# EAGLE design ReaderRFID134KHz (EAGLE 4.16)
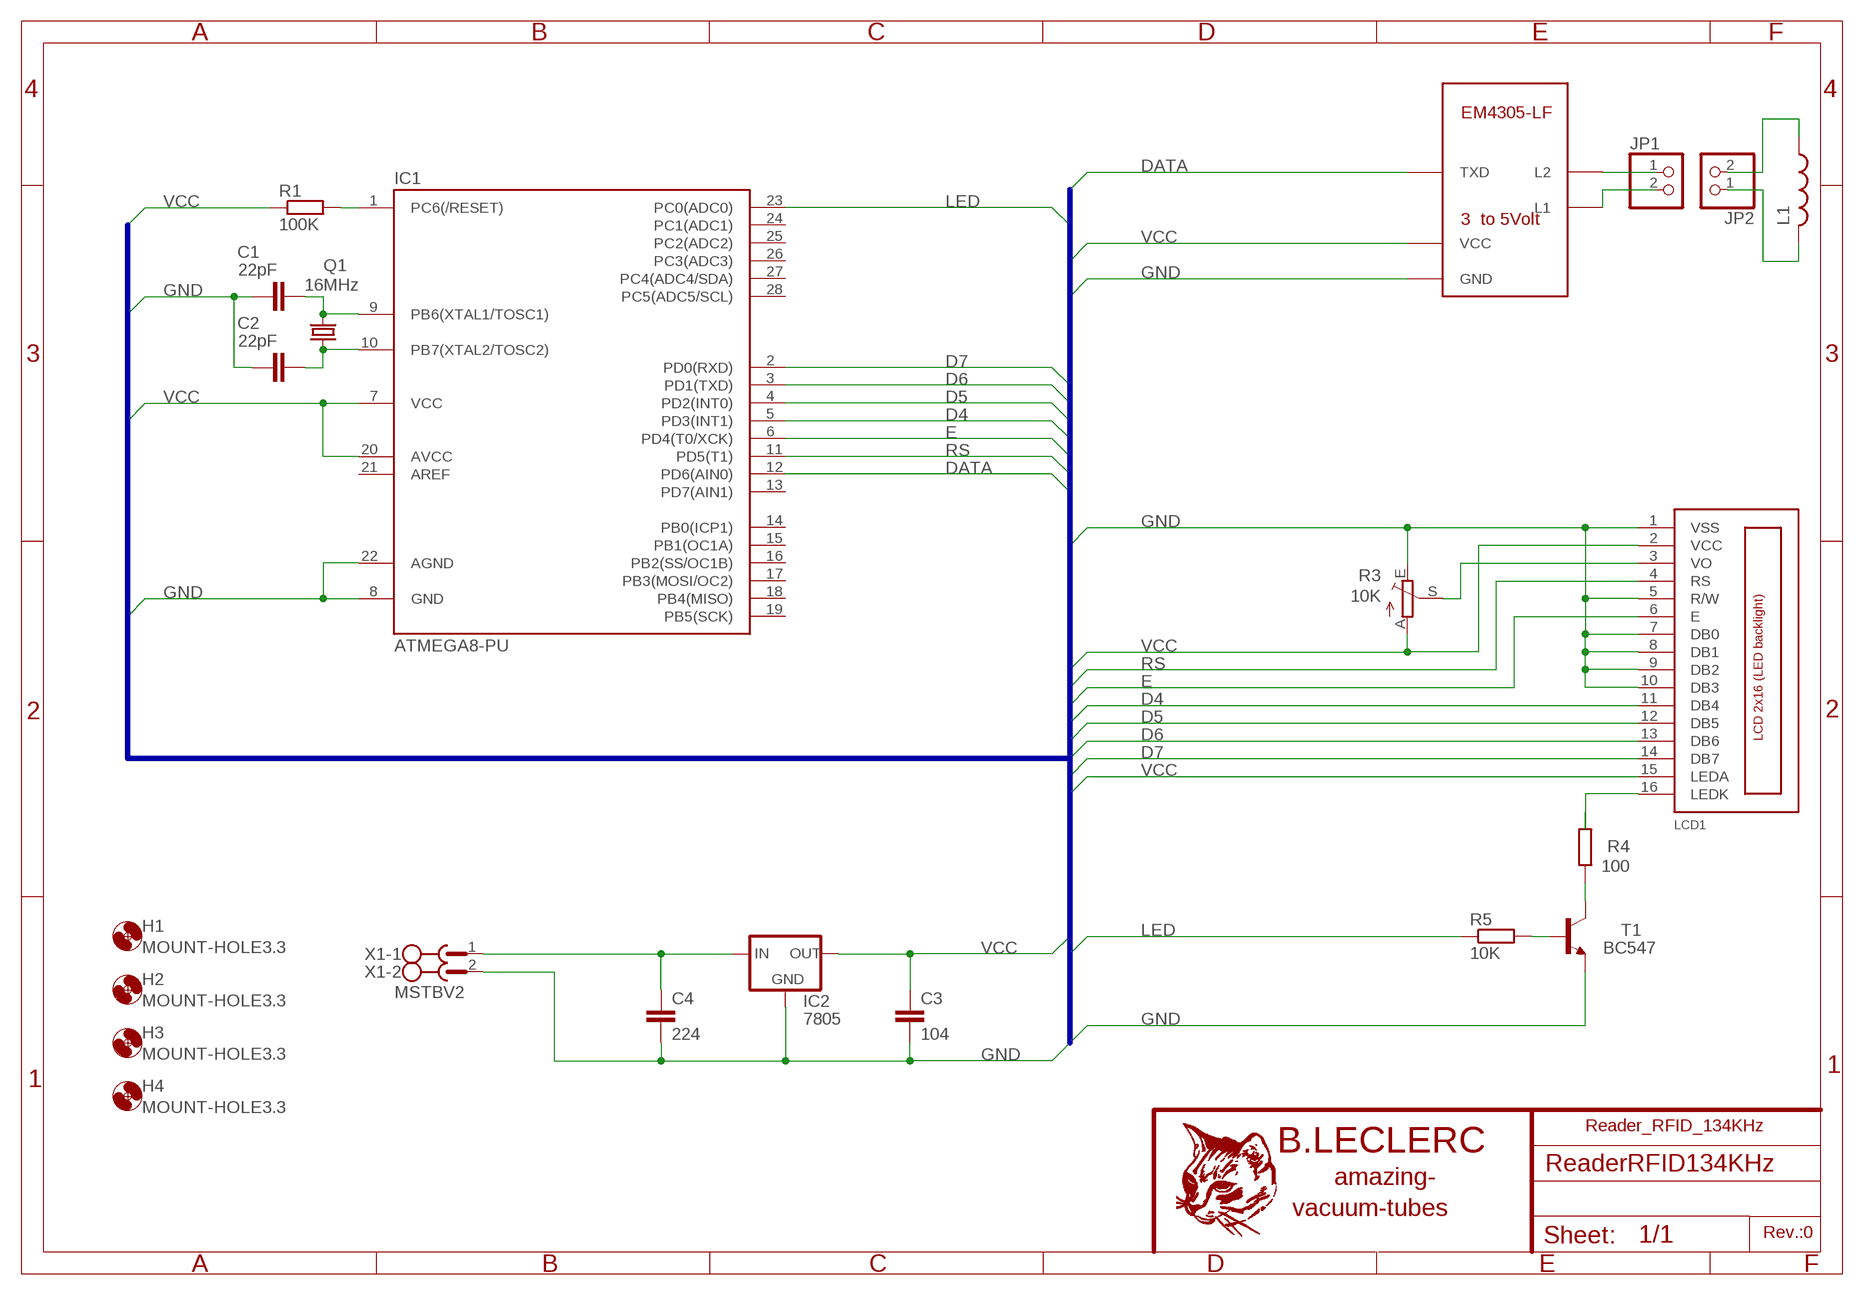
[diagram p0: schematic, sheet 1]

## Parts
C1  22pF  C-EU025-030X050  [C025-030X050]
C2  22pF  C-EU025-030X050  [C025-030X050]
C3  104  C-EU050-025X075  [C050-025X075]
C4  224  C-EU050-035X075  [C050-035X075]
H1  MOUNT-HOLE3.3  [3,3]
H2  MOUNT-HOLE3.3  [3,3]
H3  MOUNT-HOLE3.3  [3,3]
H4  MOUNT-HOLE3.3  [3,3]
IC1  ATMEGA8-PU  [DIL28-3]
IC2  7805  78XXL  [78XXL]
JP1  PINHD-1X2  [1X02]
JP2  PINHD-1X2  [1X02]
L1  L-US0207/15  [0207/15]
LCD1  LCD_2X16_SIL  [HY-1602F]
Q1  16MHz  CRYTALHC49S  [HC49/S]
R1  100K  R-EU_0207/12  [0207/12]
R3  10K  TRIM_EU-PT10  [PT-10]
R4  100  R-EU_0207/12  [0207/12]
R5  10K  R-EU_0207/12  [0207/12]
T1  BC547  BC547A-NPN-TO92-EBC  [TO92-EBC]
U$2  RECEPT_RFID_134KHZ  [RECEPT_RFID_134KHZ]
X1  MSTBV2  [MSTBV2]

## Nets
D4: IC1.5(PD3(INT1)) LCD1.11(DB4)
D5: IC1.4(PD2(INT0)) LCD1.12(DB5)
D6: IC1.3(PD1(TXD)) LCD1.13(DB6)
D7: IC1.2(PD0(RXD)) LCD1.14(DB7)
DATA: IC1.12(PD6(AIN0)) U$2.TXD
E: IC1.6(PD4(T0/XCK)) LCD1.6(E)
GND: C1.1 C2.1 C3.2 C4.2 IC1.8(GND) IC1.22(AGND) IC2.GND LCD1.1(VSS) LCD1.5(R/W) LCD1.7(DB0) LCD1.8(DB1) LCD1.9(DB2) LCD1.10(DB3) R3.E T1.E U$2.GND X1.2
LED: IC1.23(PC0(ADC0)) R5.1
N$1: JP2.2 L1.1
N$2: JP2.1 L1.2
N$3: JP1.1 U$2.L2
N$4: JP1.2 U$2.L1
N$6: LCD1.3(VO) R3.S
N$7: LCD1.16(LEDK) R4.2
N$8: R5.2 T1.B
N$9: IC1.1(PC6(/RESET)) R1.2
N$10: C1.2 IC1.9(PB6(XTAL1/TOSC1)) Q1.2
N$11: C2.2 IC1.10(PB7(XTAL2/TOSC2)) Q1.1
N$12: R4.1 T1.C
N$16: C4.1 IC2.IN X1.1
RS: IC1.11(PD5(T1)) LCD1.4(RS)
VCC: C3.1 IC1.7(VCC) IC1.20(AVCC) IC2.OUT LCD1.2(VCC) LCD1.15(LEDA) R1.1 R3.A U$2.VCC
Unconnected: IC1.13(PD7(AIN1)) IC1.14(PB0(ICP1)) IC1.15(PB1(OC1A)) IC1.16(PB2(SS/OC1B)) IC1.17(PB3(MOSI/OC2)) IC1.18(PB4(MISO)) IC1.19(PB5(SCK)) IC1.21(AREF) IC1.24(PC1(ADC1)) IC1.25(PC2(ADC2)) IC1.26(PC3(ADC3)) IC1.27(PC4(ADC4/SDA)) IC1.28(PC5(ADC5/SCL))

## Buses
B$1

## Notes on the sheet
- Reader_RFID_134KHz
- Rev.:0

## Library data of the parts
C1-C4 = rcl:C-EU: CAPACITOR, European symbol
H1-H4 = holes:MOUNT-HOLE: MOUNTING HOLE with drill center marker
IC1 = atmega8:ATMEGA8-PU
IC2 = v-reg:78XXL: VOLTAGE REGULATOR
JP1 JP2 = pinhead:PINHD-1X2: PIN HEADER
L1 = rcl:L-US: INDUCTOR, American symbol
LCD1 = lcd_2x16_led_backlight:LCD_2X16_SIL
Q1 = crystal:CRYTAL: CRYSTAL
R1 R4 R5 = rcl:R-EU_: RESISTOR, European symbol
R3 = pot:TRIM_EU-: POTENTIOMETER
T1 = transistor:*-NPN-: NPN Transistror
U$2 = Arduino:RECEPT_RFID_134KHZ
X1 = con-phoenix-508:MSTBV2: PHOENIX

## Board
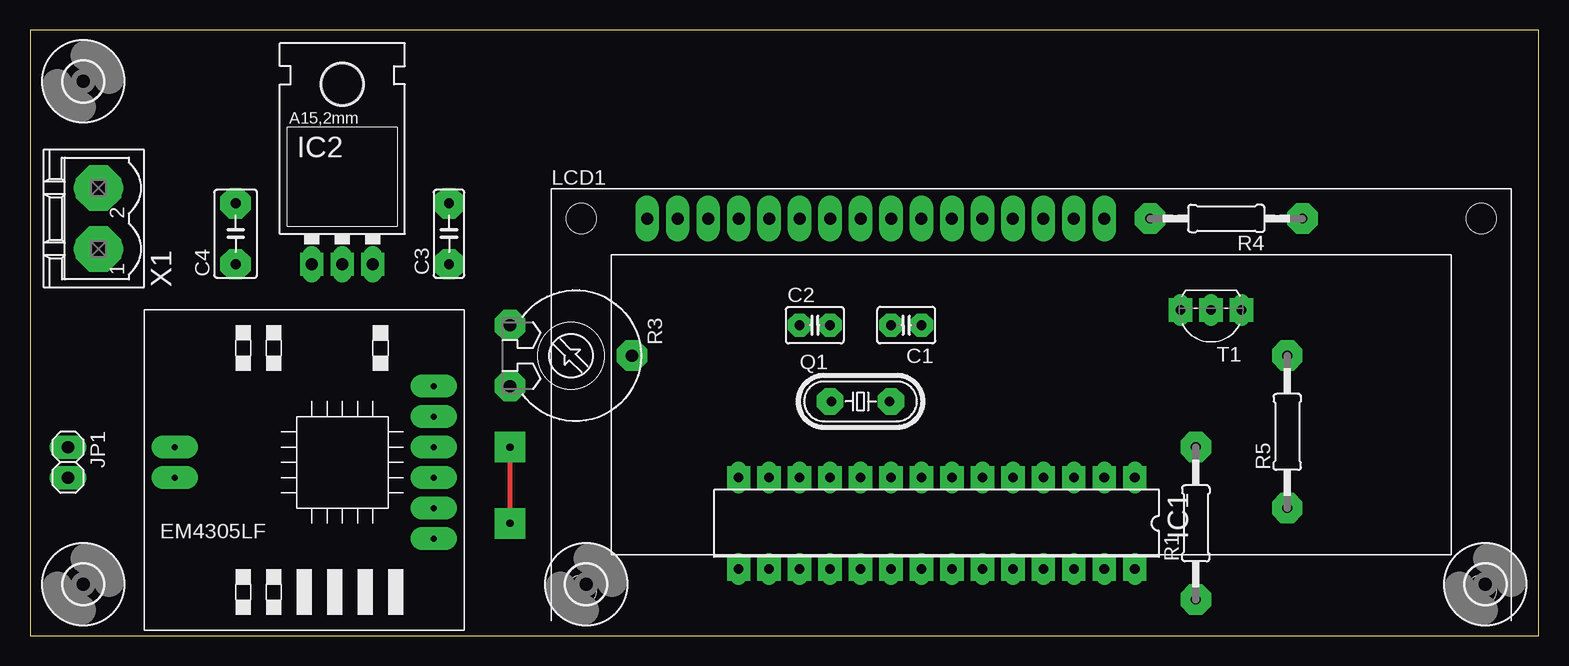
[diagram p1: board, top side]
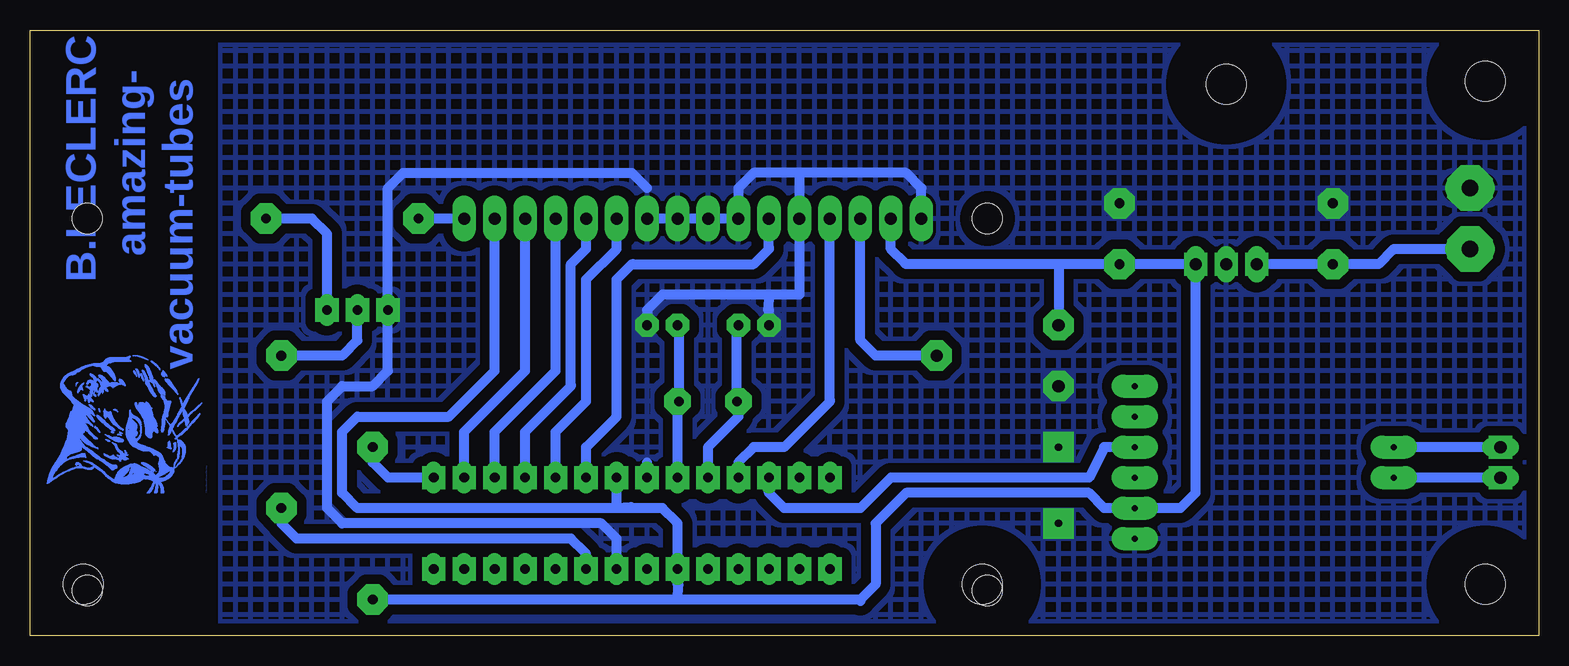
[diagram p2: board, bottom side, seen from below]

Size 125.71 x 50.47 mm. Coordinates in mm from the lower left corner, seen from the top.
Outline: 0,0 125.71,0 125.71,50.47 0,50.47 0,0
Copper layers (1*16): Top 0.035mm / dielectric 1.5mm / Bottom 0.035mm
Design rules "default": minimum track width 10mil, minimum drill 24mil, track to track 8mil, track to pad 8mil, pad to pad 8mil, via to via 8mil, smd to smd 8mil, copper to edge 40mil, drill to drill 8mil, minimum pad ring 10mil, minimum via ring 8mil, stop-mask expansion 4mil, vias tented up to drill 0mil, thermal gap 10mil

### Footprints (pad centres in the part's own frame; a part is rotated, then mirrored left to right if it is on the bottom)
C025-030X050 = drill 0.813 octagon: 1 -1.27,0; 2 1.27,0
C050-025X075 = drill 0.813 octagon: 1 -2.54,0; 2 2.54,0
C050-035X075 = drill 0.813 octagon: 1 -2.54,0; 2 2.54,0
3,3 = hole 3.3: 0,0
DIL28-3 = drill 0.813 long: 1 -16.51,-3.81; 2 -13.97,-3.81; 3 -11.43,-3.81; 4 -8.89,-3.81; 5 -6.35,-3.81; 6 -3.81,-3.81; 7 -1.27,-3.81; 8 1.27,-3.81; 9 3.81,-3.81; 10 6.35,-3.81; 11 8.89,-3.81; 12 11.43,-3.81; 13 13.97,-3.81; 14 16.51,-3.81; 15 16.51,3.81; 16 13.97,3.81; 17 11.43,3.81; 18 8.89,3.81; 19 6.35,3.81; 20 3.81,3.81; 21 1.27,3.81; 22 -1.27,3.81; 23 -3.81,3.81; 24 -6.35,3.81; 25 -8.89,3.81; 26 -11.43,3.81; 27 -13.97,3.81; 28 -16.51,3.81
78XXL = drill 1.016 long: GND 0,-3.81; IN -2.54,-3.81; OUT 2.54,-3.81 | hole 3.302: 0,11.176
1X02 = drill 1.016 long: 1 -1.27,0; 2 1.27,0
0207/15 = drill 0.813 octagon: 1 -7.62,0; 2 7.62,0
HY-1602F = drill 1 pad 1.93 long: 1 2.54,0; 2 5.08,0; 3 7.62,0; 4 10.16,0; 5 12.7,0; 6 15.24,0; 7 17.78,0; 8 20.32,0; 9 22.86,0; 10 25.4,0; 11 27.94,0; 12 30.48,0; 13 33.02,0; 14 35.56,0; 15 38.1,0; 16 40.64,0 | hole 2.5: -2.96,0; 72.04,0; -2.96,-31; 72.04,-31
HC49/S = drill 0.813 round: 1 -2.413,0; 2 2.413,0
0207/12 = drill 0.813 octagon: 1 -6.35,0; 2 6.35,0
PT-10 = drill 1.016 octagon: A -2.54,-5.08; E 2.54,-5.08; S 0,5.08
TO92-EBC = drill 0.813 long: B 0,-1.27; C -2.54,-1.27; E 2.54,-1.27
RECEPT_RFID_134KHZ = drill 0.5 pad 1.93 long: GND 2.54,19.05; L1 24.13,13.97; L2 24.13,11.43; NC 2.54,6.35; P$1 2.54,13.97; P$5 2.54,8.89; TXD 2.54,11.43; VCC 2.54,16.51
MSTBV2 = drill 1.397 long: 1 -2.54,0; 2 2.54,0

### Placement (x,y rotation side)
C1  73.02,25.87 180 top
C2  65.4,25.87 0 top
C3  34.92,33.49 90 top
C4  17.14,33.49 90 top
H1  4.44,4.28 0 top
H2  46.35,4.28 0 top
H3  121.28,4.28 0 top
H4  4.44,46.19 0 top
IC1  75.56,9.36 180 top
IC2  26.03,34.76 0 top
JP1  3.17,14.44 270 top
JP2  not placed on the board
L1  not placed on the board
LCD1  48.89,34.76 0 top
Q1  69.21,19.52 0 top
R1  97.15,9.36 90 top
R3  45.08,23.33 270 top
R4  99.69,34.76 180 top
R5  104.77,16.98 90 top
T1  98.42,25.87 180 top
U$2  36.19,27.14 180 top
U$3  [CHAT1]  111.12,11.9 90 bottom
X1  5.71,34.76 90 top

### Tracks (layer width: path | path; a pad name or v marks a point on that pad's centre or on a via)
D4
  Bottom 0.813: LCD1.11 76.83,32.22 79.37,29.68 79.37,19.62 arc45 79.44,19.45 81.91,16.98 IC1.5
D5
  Bottom 0.813: LCD1.12 79.37,32.33 arc45 79.44,32.15 80.64,30.95 80.64,20.89 arc45 80.71,20.72 84.45,16.98 IC1.4
D6
  Bottom 0.813: LCD1.13 81.91,22.16 arc45 81.98,21.99 86.99,16.98 IC1.3
D7
  Bottom 0.813: LCD1.14 84.45,22.06 89.53,16.98 IC1.2
DATA
  Bottom 0.813: U$2.TXD 36.19,15.71 37.46,13.17 53.97,13.17 56.51,10.63 62.86,10.63 64.13,11.9 IC1.12
E
  Bottom 0.813: LCD1.6 64.13,32.33 arc45 64.2,32.15 65.4,30.95 75.45,30.95 arc-45 75.63,30.88 76.83,29.68 76.83,18.36 arc45 76.9,18.18 79.37,15.71 IC1.6
GND  (via drill 0.5 pad 1.27, 0.5 pad 1.93, 0.6 pad 2.54, 0.6 pad 3.81)
  Top 0.406: v40,9.36 v40,15.71
  Bottom 0.813: IC1.8 74.29,14.44 | C2.1 64.13,27.04 arc-45 64.2,27.21 64.13,28.41 | 64.13,28.41 73.02,28.41 74.29,27.14 C1.1 | 64.13,28.41 61.59,28.41 LCD1.5 61.59,38.57 | IC1.22 76.83,8.09 78.1,9.36 99.69,9.36 100.96,10.63 100.96,19.52 99.69,20.79 97.15,20.79 95.88,22.06 T1.E 95.88,37.3 94.61,38.57 75.56,38.57 74.29,37.3 | LCD1.10 LCD1.9 LCD1.8 LCD1.7 66.67,37.3 65.4,38.57 61.59,38.57 | 61.59,38.57 52.7,38.57 51.43,37.3 LCD1.1
  other vias: 5.71,37.3 17.14,36.03 34.92,36.03 26.03,30.95 95.88,27.14 40,20.79 51.43,34.76 61.59,34.76 66.67,34.76 74.29,34.76 71.75,34.76 69.21,34.76 64.13,25.87 74.29,25.87 74.29,13.17 76.83,5.55 33.65,8.09
  pour Bottom (isolate 0.813, hatched): 0.63,50 109.85,50 109.85,0.47 0.63,0.47
LED
  Bottom 0.813: IC1.23 79.37,6.71 arc-45 79.44,6.89 80.64,8.09 103.5,8.09 104.77,9.36 R5.1
N$1  (1 unrouted)
N$2  (1 unrouted)
N$3
  Bottom 0.813: JP1.1 U$2.L2
N$4
  Bottom 0.813: JP1.2 U$2.L1
N$5  (via drill 0.5 pad 1.93)
  other vias: 23.49,30.95
N$6
  Bottom 0.813: LCD1.3 56.51,24.6 55.24,23.33 R3.S
N$7
  Bottom 0.813: LCD1.16 R4.2
N$8
  Bottom 0.813: R5.2 99.69,23.33 98.42,24.6 T1.B
N$9
  Bottom 0.813: IC1.1 95.77,13.17 arc45 95.95,13.24 97.15,14.44 R1.2
N$10
  Bottom 0.813: IC1.9 71.75,19.52 Q1.2 71.62,25.64 arc-45 71.7,25.82 C1.2
N$11
  Bottom 0.813: IC1.10 69.21,15.61 arc45 69.14,15.78 66.67,18.25 66.67,19.52 Q1.1 66.8,25.64 arc45 66.72,25.82 C2.2
N$12
  Bottom 0.813: T1.C 100.96,33.49 102.23,34.76 R4.1
N$13  (via drill 0.6 pad 2.54)
  other vias: 17.14,30.95
N$15  (via drill 0.6 pad 2.54)
  other vias: 34.92,30.95
N$16
  Bottom 0.813: X1.1 11.96,32.22 arc-45 12.13,32.15 13.33,30.95 C4.1 IC2.IN
N$17  (via drill 0.6 pad 2.54)
  other vias: 93.34,34.76
N$18  (via drill 0.6 pad 2.54)
  other vias: 106.04,34.76
N$19  (via drill 0.6 pad 2.54)
  other vias: 104.77,23.33
N$20  (via drill 0.6 pad 2.54)
  other vias: 97.15,15.71
N$21  (via drill 0.6 pad 2.54)
  other vias: 104.77,10.63
N$22  (via drill 0.6 pad 2.54)
  other vias: 97.15,3.01
N$23  (via drill 0.6 pad 2.54)
  other vias: 40,25.87
N$24  (via drill 0.5 pad 1.93)
  other vias: 66.67,25.87
N$25  (via drill 0.6 pad 2.54)
  other vias: 50.16,23.33
N$26  (via drill 0.5 pad 1.93)
  other vias: 28.57,30.95
N$27  (via drill 0.6 pad 3.81)
  other vias: 5.71,32.22
N$28  (via drill 0.5 pad 1.93)
  other vias: 3.17,15.71
N$29  (via drill 0.5 pad 1.93)
  other vias: 3.17,13.17
N$30  (via drill 0.5 pad 1.93)
  other vias: 71.75,25.87
N$31  (via drill 0.5 pad 1.93)
  other vias: 53.97,34.76
N$32  (via drill 0.5 pad 1.93)
  other vias: 56.51,34.76
N$34  (via drill 0.5 pad 1.93)
  other vias: 64.13,34.76
N$35  (via drill 0.5 pad 2.18)
  other vias: 71.75,19.52
N$36  (via drill 0.5 pad 2.18)
  other vias: 66.67,19.52
N$39  (via drill 0.5 pad 1.93)
  other vias: 76.83,34.76
N$40  (via drill 0.5 pad 1.93)
  other vias: 79.37,34.76
N$41  (via drill 0.5 pad 1.93)
  other vias: 81.91,34.76
N$42  (via drill 0.5 pad 1.93)
  other vias: 84.45,34.76
N$43  (via drill 0.5 pad 1.93)
  other vias: 86.99,34.76
N$44  (via drill 0.5 pad 1.93)
  other vias: 89.53,34.76
N$45  (via drill 0.5 pad 1.93)
  other vias: 59.05,34.76
N$47  (via drill 0.5 pad 1.93)
  other vias: 98.42,27.14
N$48  (via drill 0.5 pad 1.93)
  other vias: 100.96,27.14
N$49  (via drill 0.5 pad 1.93)
  other vias: 59.05,13.17
N$50  (via drill 0.5 pad 1.93)
  other vias: 61.59,13.17
N$51  (via drill 0.5 pad 1.93)
  other vias: 64.13,13.17
N$52  (via drill 0.5 pad 1.93)
  other vias: 66.67,13.17
N$53  (via drill 0.5 pad 1.93)
  other vias: 69.21,13.17
N$54  (via drill 0.5 pad 1.93)
  other vias: 71.75,13.17
N$55  (via drill 0.5 pad 1.93)
  other vias: 76.83,13.17
N$56  (via drill 0.5 pad 1.93)
  other vias: 79.37,13.17
N$57  (via drill 0.5 pad 1.93)
  other vias: 81.91,13.17
N$58  (via drill 0.5 pad 1.93)
  other vias: 84.45,13.17
N$59  (via drill 0.5 pad 1.93)
  other vias: 86.99,13.17
N$60  (via drill 0.5 pad 1.93)
  other vias: 89.53,13.17
N$62  (via drill 0.5 pad 1.93)
  other vias: 92.07,13.17
N$63  (via drill 0.5 pad 1.93)
  other vias: 92.07,5.55
N$64  (via drill 0.5 pad 1.93)
  other vias: 89.53,5.55
N$65  (via drill 0.5 pad 1.93)
  other vias: 86.99,5.55
N$66  (via drill 0.5 pad 1.93)
  other vias: 84.45,5.55
N$67  (via drill 0.5 pad 1.93)
  other vias: 81.91,5.55
N$68  (via drill 0.5 pad 1.93)
  other vias: 79.37,5.55
N$70  (via drill 0.5 pad 1.93)
  other vias: 74.29,5.55
N$71  (via drill 0.5 pad 1.93)
  other vias: 71.75,5.55
N$72  (via drill 0.5 pad 1.93)
  other vias: 69.21,5.55
N$73  (via drill 0.5 pad 1.93)
  other vias: 66.67,5.55
N$74  (via drill 0.5 pad 1.93)
  other vias: 64.13,5.55
N$75  (via drill 0.5 pad 1.93)
  other vias: 61.59,5.55
N$76  (via drill 0.5 pad 1.93)
  other vias: 59.05,5.55
RS
  Bottom 0.813: LCD1.4 59.05,19.62 arc45 59.12,19.45 62.86,15.71 65.4,15.71 66.67,14.44 IC1.11
VCC
  Bottom 0.813: 40,30.95 C3.1 IC2.OUT 28.57,11.9 29.77,10.7 arc45 29.95,10.63 U$2.VCC 36.19,10.63 37.46,11.9 52.7,11.9 55.24,9.36 55.24,4.28 56.44,3.08 | 40,30.95 52.6,30.95 arc45 52.77,31.02 53.97,32.22 LCD1.2 | 71.75,3.01 71.68,4.21 arc45 71.75,4.38 IC1.20 71.75,9.26 arc-45 71.82,9.43 73.02,10.63 75.45,10.63 | 71.75,3.01 56.51,3.01 56.44,3.08 | 56.44,3.08 arc-45 56.51,2.91 | 71.75,3.01 R1.1 | 75.45,10.63 arc45 75.63,10.7 76.83,10.63 | 76.83,10.63 IC1.7 | LCD1.15 86.99,22.06 90.8,18.25 98.42,18.25 99.69,16.98 99.69,11.9 98.42,10.63 76.83,10.63 | 75.45,10.63 76.83,10.63 | 40,30.95 R3.A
